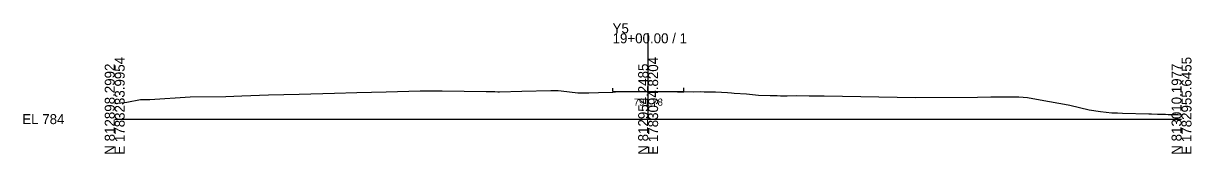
# Model space of a CAD drawing. Extents: x -26 to 1603, y -10 to 6526.
# Drawn here: x 1274.3 to 1602.8, y 5990.3 to 6026.9 of the extents above; entities that cross this region are included whole.
import ezdxf

# ---------------------------------------------------------------- set-up
doc = ezdxf.new("R2010")
doc.units = 0
for name, color, linetype in [('Exist Cross Section Cell', 7, 'Continuous'), ('Exist XS Center Line Elevation Label', 7, 'Continuous'), ('Exist XS Ground Line', 7, 'Continuous'), ('Prop XS EOT Tick Mark', 7, 'Continuous'), ('Prop XS Finish Grade Pavement', 7, 'Continuous')]:
    doc.layers.add(name, color=color, linetype=linetype)

msp = doc.modelspace()

# ---------------------------------------------------------------- linework, layer by layer
at = {"layer": 'Exist Cross Section Cell'}
for p, q in [((1450, 6000), (1450, 6024.11)), ((1300, 6000), (1450, 6000)), ((1450, 6000), (1600, 6000))]:
    msp.add_line(p, q, dxfattribs=at)
at = {"layer": 'Exist XS Ground Line'}
for p, q in [((1309.87, 6005.56), (1321.24, 6006.22)), ((1321.24, 6006.22), (1331.22, 6006.4)), ((1331.22, 6006.4), (1335.75, 6006.54)), ((1335.75, 6006.54), (1343.2, 6006.84)), ((1343.2, 6006.84), (1351.87, 6007.01)), ((1351.87, 6007.01), (1361.83, 6007.33)), ((1361.83, 6007.33), (1368.04, 6007.5)), ((1368.04, 6007.5), (1376.3, 6007.71)), ((1376.3, 6007.71), (1385.86, 6007.92)), ((1385.86, 6007.92), (1392.09, 6007.95)), ((1392.09, 6007.95), (1404.41, 6007.75)), ((1404.41, 6007.75), (1406.87, 6007.78)), ((1406.87, 6007.78), (1407.71, 6007.67)), ((1407.71, 6007.67), (1408.18, 6007.67)), ((1408.18, 6007.67), (1414.51, 6007.87)), ((1414.51, 6007.87), (1422.63, 6008.02)), ((1422.63, 6008.02), (1424.74, 6008.04)), ((1424.74, 6008.04), (1425.53, 6007.96)), ((1425.53, 6007.96), (1430.2, 6007.36)), ((1430.2, 6007.36), (1433.35, 6007.39)), ((1433.35, 6007.39), (1436.06, 6007.49)), ((1436.06, 6007.49), (1440.1, 6007.61)), ((1440.1, 6007.61), (1440.8, 6007.63)), ((1440.8, 6007.63), (1449.99, 6007.78)), ((1449.99, 6007.78), (1458.24, 6007.69)), ((1458.24, 6007.69), (1460, 6007.67)), ((1460, 6007.67), (1460.02, 6007.77)), ((1460.02, 6007.77), (1462.65, 6007.71)), ((1462.65, 6007.71), (1464.83, 6007.75)), ((1464.83, 6007.75), (1465.76, 6007.66)), ((1465.76, 6007.66), (1468.98, 6007.65)), ((1468.98, 6007.65), (1472.33, 6007.47)), ((1472.33, 6007.47), (1473.43, 6007.4)), ((1473.43, 6007.4), (1474.21, 6007.34)), ((1474.21, 6007.34), (1477.62, 6007.09)), ((1477.62, 6007.09), (1481.05, 6006.74)), ((1481.05, 6006.74), (1484.28, 6006.63)), ((1484.28, 6006.63), (1486.25, 6006.6)), ((1486.25, 6006.6), (1487.22, 6006.57)), ((1487.22, 6006.57), (1489.07, 6006.58)), ((1489.07, 6006.58), (1491.63, 6006.6)), ((1491.63, 6006.6), (1495.27, 6006.59)), ((1495.27, 6006.59), (1499.52, 6006.59)), ((1499.52, 6006.59), (1525.16, 6006.04)), ((1525.16, 6006.04), (1542.59, 6006.16)), ((1542.59, 6006.16), (1546.36, 6006.28)), ((1546.36, 6006.28), (1551.92, 6006.26)), ((1551.92, 6006.26), (1554.24, 6006.26)), ((1554.24, 6006.26), (1556.7, 6006.08)), ((1556.7, 6006.08), (1561.24, 6005.24)), ((1300, 6004.39), (1303.42, 6004.8)), ((1303.42, 6004.8), (1307.29, 6005.51)), ((1307.29, 6005.51), (1309.87, 6005.56)), ((1561.24, 6005.24), (1567.1, 6004.17)), ((1567.1, 6004.17), (1568.59, 6003.9)), ((1568.59, 6003.9), (1574, 6002.61)), ((1574, 6002.61), (1577.17, 6002.18)), ((1577.17, 6002.18), (1580.36, 6001.78)), ((1580.36, 6001.78), (1581.98, 6001.73)), ((1581.98, 6001.73), (1583.38, 6001.7)), ((1583.38, 6001.7), (1590.78, 6001.5)), ((1590.78, 6001.5), (1591.51, 6001.48)), ((1591.51, 6001.48), (1593.26, 6001.43)), ((1593.26, 6001.43), (1595.5, 6001.36)), ((1595.5, 6001.36), (1596.24, 6001.34)), ((1596.24, 6001.34), (1598.46, 6001.27)), ((1598.46, 6001.27), (1598.95, 6001.26)), ((1598.95, 6001.26), (1600, 6001.18))]:
    msp.add_line(p, q, dxfattribs=at)
at = {"layer": 'Prop XS EOT Tick Mark'}
for p, q in [((1440.1, 6007.74), (1440.1, 6008.74)), ((1460, 6007.79), (1460, 6008.79))]:
    msp.add_line(p, q, dxfattribs=at)
at = {"layer": 'Prop XS Finish Grade Pavement'}
for p, q in [((1440.1, 6007.74), (1440.8, 6007.75)), ((1440.8, 6007.75), (1449.99, 6007.9)), ((1449.99, 6007.9), (1458.24, 6007.81)), ((1458.24, 6007.81), (1460, 6007.79))]:
    msp.add_line(p, q, dxfattribs=at)

# ---------------------------------------------------------------- texts
at = {"layer": 'Exist Cross Section Cell'}
for s, p in [('Y5', (1440, 6024.11)), ('19+00.00 / 1', (1440, 6021.31)), ('EL 784', (1274, 5998.6))]:
    msp.add_text(s, height=2.8, dxfattribs=at).set_placement(p)
for s, p in [('E 1783233.9954', (1302.8, 5990)), ('N 812954.2485', (1450, 5990)), ('E 1783094.8204', (1452.8, 5990)), ('E 1782955.6455', (1602.8, 5990)), ('N 812898.2992', (1300, 5990)), ('N 813010.1977', (1600, 5990))]:
    msp.add_text(s, height=2.8, rotation=90, dxfattribs=at).set_placement(p)
at = {"layer": 'Exist XS Center Line Elevation Label'}
msp.add_text('791.78', height=2, dxfattribs=at).set_placement((1445.96, 6003.78))

doc.saveas('drawing.dxf')
